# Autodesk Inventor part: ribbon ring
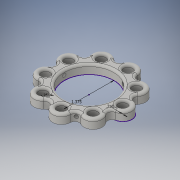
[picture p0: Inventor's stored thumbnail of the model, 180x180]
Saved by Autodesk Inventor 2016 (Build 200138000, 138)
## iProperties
Created: 2015-10
Part Number: ribbon ring
Material: Generic
Document SubType Name: Modeling
Designer: Z
Density: 1 g/cm^3
Appearance: Default
Author: Z
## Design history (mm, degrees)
sketch "Sketch1"
  geometry: C1 r 17.463 at (0, 0); C2 r 3.175 at (-23.812, 0); C3 r 6.35 at (-23.812, 0); 2 further points
  constraints: 3 centre point, 3 coincident, 2 horizontal alignment, 1 tangent, 2 other
  dimensions: "d0" = 34.925 diameter of C1; "d1" = 6.35 dimension on C1; "d10" = 6.35 diameter of C2
extrude "Extrusion1" new body sketch "Sketch1" distance "d3" = 6.35; taper "d4" = 0 deg
extrude "Extrusion3" join sketch "Sketch1" stored distance "d11" = 6.35; taper "d12" = 0 deg
extrude "Extrusion4" cut sketch "Sketch1" stored distance "d13" = 6.35; taper "d14" = 0 deg
pattern_circular "Circular Pattern2" dims angle "d16" = 360 deg
fillet "Fillet1" dims "d18" = 3.175
sketch "Sketch2"
  geometry: L1 (0, 28.27)-(6.35, 28.27) reference; L2 (6.35, 28.27)-(6.35, 17.463) reference; L3 (6.35, 17.463)-(0, 17.463) reference; L4 (0, 17.463)-(0, 28.27) reference; L5 (6.35, -28.27)-(0, -28.27) reference; L6 (0, -28.27)-(0, -17.463) reference; L7 (0, -17.463)-(6.35, -17.463) reference; L8 (6.35, -17.463)-(6.35, -28.27) reference; L9 (6.35, 17.463)-(0, -17.463); 2 further points
  constraints: 2 end point, 1 midpoint
hole "Hole1" sketch "Sketch2" at (3.175, 0) diameter "d19" = 2.4638; stored, may be unused: countersink angle "d23" = 82 deg, drill point angle "d25" = 118 deg; dims "d20" = 5.9944, "d21" = 9.525, "d22" = 6.35, "d24" = 8.7884
pattern_circular "Circular Pattern3" dims angle "d27" = 360 deg
fillet "Fillet2" dims "d29" = 1.5875
body "Solid1"
node "Project Cut Edges1"
